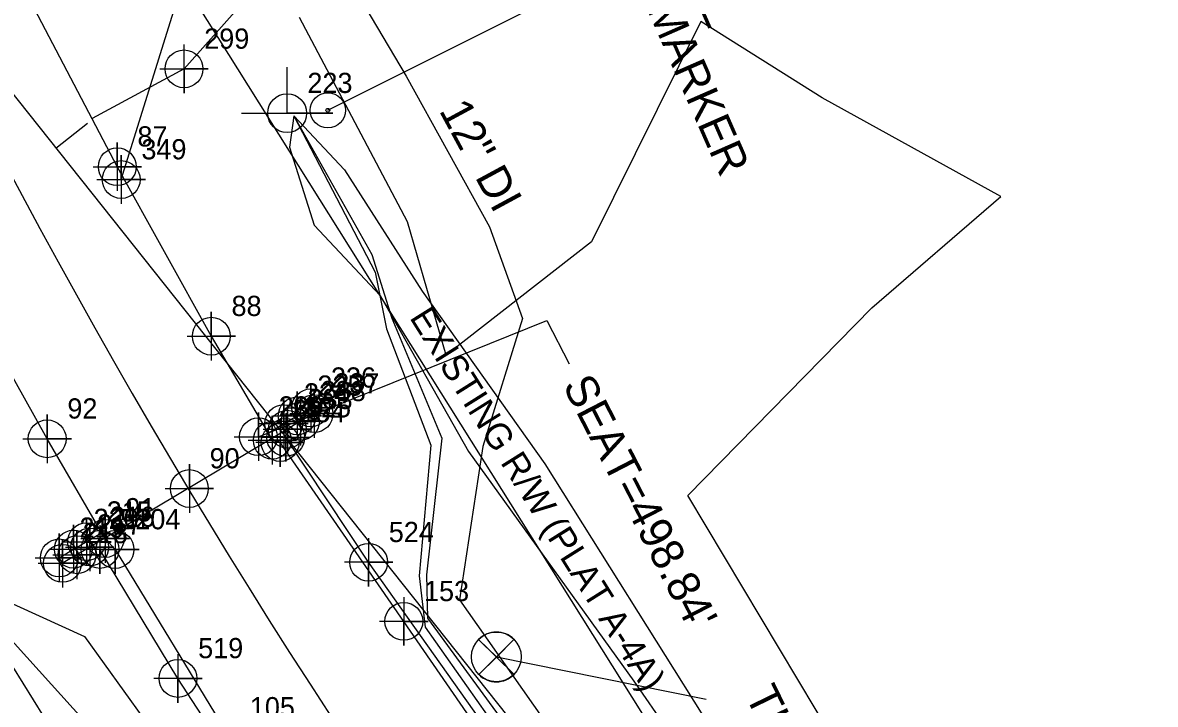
# Model space of a CAD drawing. Extents: x 1534145 to 1537876, y 509021 to 513201.
# Drawn here: x 1536125.4 to 1536265.6, y 511649.3 to 511733.6 of the extents above; entities that cross this region are included whole.
import ezdxf

# ---------------------------------------------------------------- set-up
doc = ezdxf.new("R2010")
doc.units = 0
for name, color, linetype in [('Exist Guardrail', 7, 'Continuous'), ('Exist Guardrail Cogo Number', 7, 'Continuous'), ('Exist Guardrail Cogo Point CELL', 7, 'Continuous'), ('Exist Horizontal Alignment', 7, 'Continuous'), ('Exist Horizontal Baseline Alignment', 7, 'Continuous'), ('Exist Horizontal Baseline Alignment Tick small', 7, 'Continuous'), ('Exist Hydro Jurisdictional Stream or Body of Water', 7, 'Continuous'), ('Exist Hydro Stream or Body of Water Cogo Number', 7, 'Continuous'), ('Exist Hydro Stream or Body of Water Cogo Point CELL', 7, 'Continuous'), ('Exist Right of Way Line', 7, 'Continuous'), ('Exist Right of Way Line Text', 7, 'Continuous'), ('Exist Roads EOP', 7, 'Continuous'), ('Exist Roads EOP Cogo Number', 7, 'Continuous'), ('Exist Roads EOP Cogo Point CELL', 7, 'Continuous'), ('Exist Structure Major Bridge Seat Cogo Number', 7, 'Continuous'), ('Exist Structure Major Bridge Seat Cogo Point CELL', 7, 'Continuous'), ('Exist Structure Major Bridge Seat Top Elevation', 7, 'Continuous'), ('Exist Structure Major Bridge WW', 7, 'Continuous'), ('Exist Structure Major Bridge WW Cogo Number', 7, 'Continuous'), ('Exist Structure Major Bridge WW Cogo Point CELL', 7, 'Continuous'), ('Exist Structure Major Deck Tunnel Box Culvert', 7, 'Continuous'), ('Exist Structure Major Deck Tunnel Box Culvert Cogo Number', 7, 'Continuous'), ('Exist Structure Major Deck Tunnel Box Culvert Cogo Point CELL', 7, 'Continuous'), ('Exist Utilities Other Located Object CELL', 7, 'Continuous'), ('Exist Utilities Other Located Object Leader', 7, 'Continuous'), ('Exist Utilities Other Located Object Text', 7, 'Continuous'), ('Exist Utilities Telephone Joint Use Power CELL', 7, 'Continuous'), ('Exist Utilities Telephone Joint Use Power Cogo Number', 7, 'Continuous'), ('Exist Utilities Telephone UG Cable', 7, 'Continuous'), ('Exist Utilities Telephone UG FO SUE', 7, 'Continuous'), ('Exist Utilities TV UG Cable', 7, 'Continuous'), ('Exist Utilities Water Test Hole SUE CELL', 7, 'Continuous'), ('Exist Utilities Water Test Hole SUE Leader', 7, 'Continuous'), ('Exist Utilities Water Test Hole SUE Text', 7, 'Continuous'), ('Exist Utilities Water UG Line SUE', 7, 'Continuous'), ('Exist Utilities Water UG Line SUE Text', 7, 'Continuous'), ('Exist Vegetation Woods Line', 7, 'Continuous')]:
    doc.layers.add(name, color=color, linetype=linetype)

# ---------------------------------------------------------------- blocks, each defined once
blk = doc.blocks.new('EXIST UTILITIES TELEPHONE JOINT USE POWER')
at = {"layer": 'Exist Utilities Telephone Joint Use Power CELL'}
blk.add_line((0, 0), (0, 0), dxfattribs=at)
blk.add_lwpolyline([(-0.1135, 0), (0.11325, 0), (0, 0), (0, 0.1135)], dxfattribs=at)
blk.add_circle((0, 0), 0.04813, dxfattribs=at)
blk = doc.blocks.new('EXIST UTILITIES OTHER LOCATED OBJECT')
at = {"layer": 'Exist Utilities Other Located Object CELL'}
for radius in [0.0436, 0.0048]:
    blk.add_circle((0, 0), radius, dxfattribs=at)

msp = doc.modelspace()

# ---------------------------------------------------------------- linework, layer by layer
at = {"layer": 'Exist Guardrail'}
for points in [[(1536245.27, 511565.91), (1536222.87, 511592.31), (1536199.87, 511622.21), (1536168.21, 511666.86), (1536157.96, 511682.31)], [(1536219.44, 511549.72), (1536199.42, 511575.71), (1536179.46, 511601.63), (1536159.41, 511629.75), (1536144.62, 511652.49), (1536134.97, 511668.45)]]:
    msp.add_lwpolyline(points, dxfattribs=at)
at = {"layer": 'Exist Guardrail Cogo Point CELL'}
for points in [[(1536157.96, 511685.31), (1536157.96, 511679.31), (1536157.96, 511682.31), (1536160.96, 511682.31), (1536154.96, 511682.31)], [(1536134.97, 511671.45), (1536134.97, 511665.45), (1536134.97, 511668.45), (1536137.97, 511668.45), (1536131.97, 511668.45)], [(1536168.21, 511669.86), (1536168.21, 511663.86), (1536168.21, 511666.86), (1536171.21, 511666.86), (1536165.21, 511666.86)], [(1536144.62, 511655.49), (1536144.62, 511649.49), (1536144.62, 511652.49), (1536147.62, 511652.49), (1536141.62, 511652.49)]]:
    msp.add_lwpolyline(points, dxfattribs=at)
for centre in [(1536157.96, 511682.31), (1536134.97, 511668.45), (1536168.21, 511666.86), (1536144.62, 511652.49)]:
    msp.add_circle(centre, 2.34, dxfattribs=at)
at = {"layer": 'Exist Horizontal Alignment'}
msp.add_arc((1536874.85, 512113.15), 850, 183.46397, 223.9944, dxfattribs=at)
at = {"layer": 'Exist Horizontal Baseline Alignment'}
msp.add_line((1536066.28, 511797.6), (1536449.44, 511315.8), dxfattribs=at)
at = {"layer": 'Exist Horizontal Baseline Alignment Tick small'}
msp.add_line((1536129.52, 511718.08), (1536133.43, 511721.19), dxfattribs=at)
at = {"layer": 'Exist Hydro Jurisdictional Stream or Body of Water'}
msp.add_lwpolyline([(1536335.49, 511814.56), (1536325.53, 511816.55), (1536309.52, 511807.77), (1536300.12, 511816.18), (1536280.82, 511820.16), (1536257.34, 511811.3), (1536245.14, 511798.71), (1536235.14, 511783.97), (1536186.51, 511760.46), (1536168.81, 511754.29), (1536145.37, 511727.9), (1536134, 511721.76)], dxfattribs=at)
at = {"layer": 'Exist Hydro Stream or Body of Water Cogo Point CELL'}
msp.add_lwpolyline([(1536142.37, 511727.9), (1536148.37, 511727.9), (1536145.37, 511727.9), (1536145.37, 511724.9), (1536145.37, 511730.9)], dxfattribs=at)
msp.add_circle((1536145.37, 511727.9), 2.34, dxfattribs=at)
at = {"layer": 'Exist Right of Way Line'}
msp.add_lwpolyline([(1536145.81, 511737.79), (1536209.6, 511636.11), (1536268.44, 511561.44), (1536375.73, 511456.33), (1536489.24, 511358.86)], dxfattribs=at)
msp.add_arc((1536874.85, 512113.15), 880, 183.46397, 223.9944, dxfattribs=at)
at = {"layer": 'Exist Roads EOP'}
for points in [[(1536369.08, 511439.8), (1536328.72, 511476.49), (1536308.15, 511496.03), (1536288.57, 511515.64), (1536269.45, 511535.94), (1536251.94, 511555.57), (1536234.04, 511576.56), (1536217.6, 511596.97), (1536202.04, 511617.77), (1536187.32, 511638.14), (1536172.57, 511659.55), (1536157.27, 511681.68), (1536156.29, 511681.96)], [(1536135.62, 511669.8), (1536136.84, 511668.44), (1536151.02, 511645.18), (1536165.85, 511623.21), (1536181.37, 511602.23), (1536197.41, 511581.17), (1536214.48, 511560.17), (1536232.66, 511538.69), (1536250.52, 511518.58), (1536269.89, 511498.04), (1536290.03, 511477.85), (1536311.06, 511457.59), (1536352.37, 511420.24), (1536394.3, 511383.89), (1536395.14, 511383.19)]]:
    msp.add_lwpolyline(points, dxfattribs=at)
at = {"layer": 'Exist Roads EOP Cogo Point CELL'}
for points in [[(1536157.27, 511684.68), (1536157.27, 511678.68), (1536157.27, 511681.68), (1536160.27, 511681.68), (1536154.27, 511681.68)], [(1536136.84, 511671.44), (1536136.84, 511665.44), (1536136.84, 511668.44), (1536139.84, 511668.44), (1536133.84, 511668.44)], [(1536172.57, 511662.55), (1536172.57, 511656.55), (1536172.57, 511659.55), (1536175.57, 511659.55), (1536169.57, 511659.55)]]:
    msp.add_lwpolyline(points, dxfattribs=at)
for centre in [(1536157.27, 511681.68), (1536136.84, 511668.44), (1536172.57, 511659.55)]:
    msp.add_circle(centre, 2.34, dxfattribs=at)
at = {"layer": 'Exist Structure Major Bridge Seat Cogo Point CELL'}
for points in [[(1536134.6, 511714.21), (1536140.6, 511714.21), (1536137.6, 511714.21), (1536137.6, 511717.21), (1536137.6, 511711.21)], [(1536151.58, 511682.39), (1536157.58, 511682.39), (1536154.58, 511682.39), (1536154.58, 511685.39), (1536154.58, 511679.39)]]:
    msp.add_lwpolyline(points, dxfattribs=at)
for centre in [(1536137.6, 511714.21), (1536154.58, 511682.39)]:
    msp.add_circle(centre, 2.34, dxfattribs=at)
at = {"layer": 'Exist Structure Major Bridge Seat Top Elevation'}
for points in [[(1536137.6, 511714.21), (1536173.26, 511828.54), (1536170.51, 511833.87)], [(1536154.58, 511682.39), (1536190.28, 511696.76), (1536193.03, 511691.43)]]:
    msp.add_lwpolyline(points, dxfattribs=at)
at = {"layer": 'Exist Structure Major Bridge WW'}
for points in [[(1536155.77, 511682.84), (1536157.72, 511684.01), (1536159.38, 511684.97), (1536161.05, 511685.97), (1536161.46, 511685.25), (1536159.78, 511684.3), (1536158.16, 511683.32)], [(1536158.16, 511683.32), (1536133.7, 511668.74), (1536132.12, 511667.79), (1536130.33, 511666.73), (1536129.94, 511667.4), (1536131.68, 511668.48), (1536133.31, 511669.4), (1536135.2, 511670.53)]]:
    msp.add_lwpolyline(points, dxfattribs=at)
at = {"layer": 'Exist Structure Major Bridge WW Cogo Point CELL'}
for points in [[(1536158.05, 511685.97), (1536164.05, 511685.97), (1536161.05, 511685.97), (1536161.05, 511688.97), (1536161.05, 511682.97)], [(1536156.38, 511684.97), (1536162.38, 511684.97), (1536159.38, 511684.97), (1536159.38, 511687.97), (1536159.38, 511681.97)], [(1536156.78, 511684.3), (1536162.78, 511684.3), (1536159.78, 511684.3), (1536159.78, 511687.3), (1536159.78, 511681.3)], [(1536158.46, 511685.25), (1536164.46, 511685.25), (1536161.46, 511685.25), (1536161.46, 511688.25), (1536161.46, 511682.25)], [(1536154.72, 511684.01), (1536160.72, 511684.01), (1536157.72, 511684.01), (1536157.72, 511687.01), (1536157.72, 511681.01)], [(1536155.16, 511683.32), (1536161.16, 511683.32), (1536158.16, 511683.32), (1536158.16, 511686.32), (1536158.16, 511680.32)], [(1536130.31, 511669.4), (1536136.31, 511669.4), (1536133.31, 511669.4), (1536133.31, 511672.4), (1536133.31, 511666.4)], [(1536130.7, 511668.74), (1536136.7, 511668.74), (1536133.7, 511668.74), (1536133.7, 511671.74), (1536133.7, 511665.74)], [(1536126.94, 511667.4), (1536132.94, 511667.4), (1536129.94, 511667.4), (1536129.94, 511670.4), (1536129.94, 511664.4)], [(1536128.68, 511668.48), (1536134.68, 511668.48), (1536131.68, 511668.48), (1536131.68, 511671.48), (1536131.68, 511665.48)], [(1536129.12, 511667.79), (1536135.12, 511667.79), (1536132.12, 511667.79), (1536132.12, 511670.79), (1536132.12, 511664.79)], [(1536127.33, 511666.73), (1536133.33, 511666.73), (1536130.33, 511666.73), (1536130.33, 511669.73), (1536130.33, 511663.73)]]:
    msp.add_lwpolyline(points, dxfattribs=at)
for centre in [(1536159.38, 511684.97), (1536161.05, 511685.97), (1536161.46, 511685.25), (1536157.72, 511684.01), (1536159.78, 511684.3), (1536158.16, 511683.32), (1536133.31, 511669.4), (1536131.68, 511668.48), (1536133.7, 511668.74), (1536129.94, 511667.4), (1536130.33, 511666.73), (1536132.12, 511667.79)]:
    msp.add_circle(centre, 2.34, dxfattribs=at)
at = {"layer": 'Exist Structure Major Deck Tunnel Box Culvert'}
for points in [[(1536105.42, 511780.89), (1536115.2, 511759.28), (1536125.98, 511737.05), (1536137.11, 511715.8), (1536148.75, 511694.83), (1536156.18, 511682.15)], [(1536135.59, 511669.86), (1536128.44, 511682.14), (1536116.19, 511704.01), (1536104.56, 511726.45), (1536093.39, 511749.41), (1536083.48, 511771.29)]]:
    msp.add_lwpolyline(points, dxfattribs=at)
at = {"layer": 'Exist Structure Major Deck Tunnel Box Culvert Cogo Point CELL'}
for points in [[(1536134.11, 511715.8), (1536140.11, 511715.8), (1536137.11, 511715.8), (1536137.11, 511718.8), (1536137.11, 511712.8)], [(1536145.75, 511694.83), (1536151.75, 511694.83), (1536148.75, 511694.83), (1536148.75, 511697.83), (1536148.75, 511691.83)], [(1536125.44, 511682.14), (1536131.44, 511682.14), (1536128.44, 511682.14), (1536128.44, 511685.14), (1536128.44, 511679.14)], [(1536153.29, 511681.96), (1536159.29, 511681.96), (1536156.29, 511681.96), (1536156.29, 511684.96), (1536156.29, 511678.96)], [(1536143.04, 511675.98), (1536149.04, 511675.98), (1536146.04, 511675.98), (1536146.04, 511678.98), (1536146.04, 511672.98)], [(1536132.62, 511669.8), (1536138.62, 511669.8), (1536135.62, 511669.8), (1536135.62, 511672.8), (1536135.62, 511666.8)]]:
    msp.add_lwpolyline(points, dxfattribs=at)
for centre in [(1536137.11, 511715.8), (1536148.75, 511694.83), (1536128.44, 511682.14), (1536156.29, 511681.96), (1536146.04, 511675.98), (1536135.62, 511669.8)]:
    msp.add_circle(centre, 2.34, dxfattribs=at)
at = {"layer": 'Exist Utilities Other Located Object Leader'}
msp.add_lwpolyline([(1536163.17, 511722.78), (1536195.35, 511738.93)], dxfattribs=at)
at = {"layer": 'Exist Utilities Telephone UG Cable'}
for p, q in [((1536158.96, 511722.08), (1536169.03, 511702.76)), ((1536158.96, 511722.08), (1536168.61, 511704.95)), ((1536168.61, 511704.95), (1536171.07, 511697.06)), ((1536169.03, 511702.76), (1536170.41, 511695.75)), ((1536171.07, 511697.06), (1536177.29, 511682.22)), ((1536170.41, 511695.75), (1536175.9, 511681.36)), ((1536177.29, 511682.22), (1536175.38, 511665.3)), ((1536175.9, 511681.36), (1536174.49, 511665.2)), ((1536174.49, 511665.2), (1536175.22, 511658.83)), ((1536175.38, 511665.3), (1536175.52, 511659.96)), ((1536175.52, 511659.96), (1536192.01, 511637.35)), ((1536175.22, 511658.83), (1536191.1, 511636.32))]:
    msp.add_line(p, q, dxfattribs=at)
msp.add_lwpolyline([(1536104.49, 511678.82), (1536164.53, 511612.35), (1536236.27, 511525.03), (1536297.08, 511464.63), (1536480.23, 511304.96), (1536615.57, 511192.85), (1536668.9, 511150.89)], dxfattribs=at)
at = {"layer": 'Exist Utilities Telephone UG FO SUE'}
for p, q in [((1536158.96, 511722.08), (1536165.22, 511715.4)), ((1536165.22, 511715.4), (1536174.85, 511700.4)), ((1536174.85, 511700.4), (1536190.04, 511679.02)), ((1536190.04, 511679.02), (1536212.07, 511643.97))]:
    msp.add_line(p, q, dxfattribs=at)
at = {"layer": 'Exist Utilities TV UG Cable'}
for p, q in [((1536158.96, 511722.08), (1536158.41, 511718.22)), ((1536158.41, 511718.22), (1536161.48, 511708.58)), ((1536161.48, 511708.58), (1536169.66, 511699.88)), ((1536169.66, 511699.88), (1536180.57, 511680.55)), ((1536180.57, 511680.55), (1536201.03, 511652.14)), ((1536201.03, 511652.14), (1536219.66, 511625.48))]:
    msp.add_line(p, q, dxfattribs=at)
at = {"layer": 'Exist Utilities Water Test Hole SUE CELL'}
for points in [[(1536181.85, 511652.97), (1536186.19, 511657.32), (1536184.02, 511655.14), (1536186.19, 511653.01), (1536181.82, 511657.32)], [(1536181.83, 511657.31), (1536184.02, 511655.15), (1536184.02, 511655.15), (1536186.19, 511657.32), (1536186.19, 511657.32)], [(1536186.21, 511652.99), (1536186.19, 511653.01), (1536184.02, 511655.14), (1536181.85, 511652.97)]]:
    msp.add_lwpolyline(points, dxfattribs=at)
msp.add_circle((1536184.02, 511655.15), 3.08, dxfattribs=at)
for start, end in [(45, 135.3289), (225.1651, 315.4953)]:
    msp.add_arc((1536184.02, 511655.15), 3.08, start, end, dxfattribs=at)
at = {"layer": 'Exist Utilities Water Test Hole SUE Leader'}
msp.add_lwpolyline([(1536184.02, 511655.15), (1536209.98, 511649.94)], dxfattribs=at)
at = {"layer": 'Exist Utilities Water UG Line SUE'}
for p, q in [((1536164.44, 511741.24), (1536172.86, 511727)), ((1536172.86, 511727), (1536183.18, 511708.38)), ((1536183.18, 511708.38), (1536187.26, 511697.03)), ((1536187.26, 511697.03), (1536182.35, 511681.2)), ((1536182.35, 511681.2), (1536179.48, 511662.22)), ((1536179.48, 511662.22), (1536193.31, 511642.54))]:
    msp.add_line(p, q, dxfattribs=at)
at = {"layer": 'Exist Vegetation Woods Line'}
for points in [[(1536364.55, 511576.16), (1536373, 511565.43), (1536358.52, 511548.6), (1536355.99, 511534.94), (1536336.01, 511558.77), (1536332.84, 511549.1), (1536313.82, 511551.08), (1536307.55, 511548.5), (1536253.81, 511613.18), (1536228.12, 511640.97), (1536207.73, 511675.11), (1536230.48, 511698.35), (1536246.44, 511712.1), (1536224.35, 511724.34), (1536209.33, 511733.76), (1536195.78, 511706.5), (1536177.81, 511692.48), (1536173.01, 511708.97), (1536159.67, 511734.26)], [(1536109.6, 511695.77), (1536115.59, 511681.18), (1536116.46, 511672.95), (1536121.81, 511662.79), (1536133.05, 511657.69), (1536145.22, 511640.75), (1536149.74, 511627.98), (1536149.55, 511621.39), (1536157.47, 511608.2), (1536169.29, 511591.2), (1536177.58, 511580.25), (1536184.9, 511566.94), (1536193.3, 511551.02), (1536202.62, 511540.69), (1536202.07, 511534.62), (1536190.4, 511542.98), (1536181.32, 511550.16), (1536169.1, 511563.16), (1536162.92, 511571.77), (1536157.34, 511582.36), (1536158.92, 511591.44), (1536156.48, 511596.06), (1536149.2, 511588.33), (1536132.43, 511602.57)]]:
    msp.add_lwpolyline(points, dxfattribs=at)

# ---------------------------------------------------------------- block references
at = {"layer": 'Exist Utilities Other Located Object CELL', "xscale": 50, "yscale": 50}
msp.add_blockref('EXIST UTILITIES OTHER LOCATED OBJECT', (1536163.17, 511722.78), dxfattribs=at)
at = {"layer": 'Exist Utilities Telephone Joint Use Power CELL', "xscale": 50, "yscale": 50}
msp.add_blockref('EXIST UTILITIES TELEPHONE JOINT USE POWER', (1536158.14, 511722.42), dxfattribs=at)

# ---------------------------------------------------------------- texts
at = {"layer": 'Exist Guardrail Cogo Number'}
for s, p in [('525', (1536160.46, 511684.81)), ('520', (1536137.47, 511670.95)), ('524', (1536170.71, 511669.36)), ('519', (1536147.12, 511654.99))]:
    msp.add_text(s, height=2.5, dxfattribs=at).set_placement(p)
at = {"layer": 'Exist Hydro Stream or Body of Water Cogo Number'}
msp.add_text('299', height=2.5, dxfattribs=at).set_placement((1536147.87, 511730.4))
at = {"layer": 'Exist Right of Way Line Text'}
msp.add_text('EXISTING R/W (PLAT A-4A)', height=3.2, rotation=302.1032, dxfattribs=at).set_placement((1536173.21, 511697.14))
at = {"layer": 'Exist Roads EOP Cogo Number'}
for s, p in [('154', (1536159.77, 511684.18)), ('104', (1536139.34, 511670.94)), ('153', (1536175.07, 511662.05)), ('105', (1536153.52, 511647.68))]:
    msp.add_text(s, height=2.5, dxfattribs=at).set_placement(p)
at = {"layer": 'Exist Structure Major Bridge Seat Cogo Number'}
for s, p in [('349', (1536140.1, 511716.71)), ('239', (1536157.08, 511684.89))]:
    msp.add_text(s, height=2.5, dxfattribs=at).set_placement(p)
at = {"layer": 'Exist Structure Major Bridge Seat Top Elevation'}
msp.add_text("SEAT=498.84'", height=4, rotation=297.2825, dxfattribs=at).set_placement((1536192.17, 511688.74))
at = {"layer": 'Exist Structure Major Bridge WW Cogo Number'}
for s, p in [('235', (1536161.88, 511687.47)), ('236', (1536163.55, 511688.47)), ('237', (1536163.96, 511687.75)), ('234', (1536160.22, 511686.51)), ('238', (1536162.28, 511686.8)), ('233', (1536160.66, 511685.82)), ('220', (1536134.18, 511670.98)), ('215', (1536135.81, 511671.9)), ('216', (1536136.2, 511671.24)), ('219', (1536132.44, 511669.9)), ('218', (1536132.83, 511669.23)), ('217', (1536134.62, 511670.29))]:
    msp.add_text(s, height=2.5, dxfattribs=at).set_placement(p)
at = {"layer": 'Exist Structure Major Deck Tunnel Box Culvert Cogo Number'}
for s, p in [('87', (1536139.61, 511718.3)), ('88', (1536151.25, 511697.33)), ('92', (1536130.94, 511684.64)), ('89', (1536158.79, 511684.46)), ('90', (1536148.54, 511678.48)), ('91', (1536138.12, 511672.3))]:
    msp.add_text(s, height=2.5, dxfattribs=at).set_placement(p)
at = {"layer": 'Exist Utilities Other Located Object Text'}
for s, p in [('TELEPHONE MARKER', (1536189.04, 511766.34)), ('ALLTELL', (1536201.37, 511753.14))]:
    msp.add_text(s, height=4, rotation=293.6544, dxfattribs=at).set_placement(p)
at = {"layer": 'Exist Utilities Telephone Joint Use Power Cogo Number'}
msp.add_text('223', height=2.5, dxfattribs=at).set_placement((1536160.64, 511724.92))
at = {"layer": 'Exist Utilities Water Test Hole SUE Text'}
msp.add_text('TH #1', height=4, rotation=295.9542, dxfattribs=at).set_placement((1536214.76, 511650.41))
at = {"layer": 'Exist Utilities Water UG Line SUE Text'}
msp.add_text('12" DI', height=4, rotation=298.4268, dxfattribs=at).set_placement((1536176.87, 511722.76))

doc.saveas('drawing.dxf')
